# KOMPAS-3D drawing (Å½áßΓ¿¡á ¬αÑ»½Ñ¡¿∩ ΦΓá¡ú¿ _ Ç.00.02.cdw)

Views: Спереди 1, Спереди, Проекционный вид 2, Изометрия XYZ 3, Изометрия XYZ
Referenced files in C:\Users\s.slezkin\Desktop\Раскатчик арок 2\: Пластина крепления штанги _ А.00.02.m3d
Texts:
  Пластина крепления штанги
  http://vk.com/sergey_krd
  Пластина
  крепления штанги
Dimensions and other numbers on the sheet: 5; 39,96; 8; 97,2; 24,01; 6; 41,98; 32; 34; 25,03; 8,5; 3 отв.; 9,5; 4,17; 1:1; 1; 0,12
